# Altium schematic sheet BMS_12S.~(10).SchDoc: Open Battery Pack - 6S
size A3; Author: Morgane Vallée; Revision: 1.0; SheetNumber: 3; SheetTotal: 4
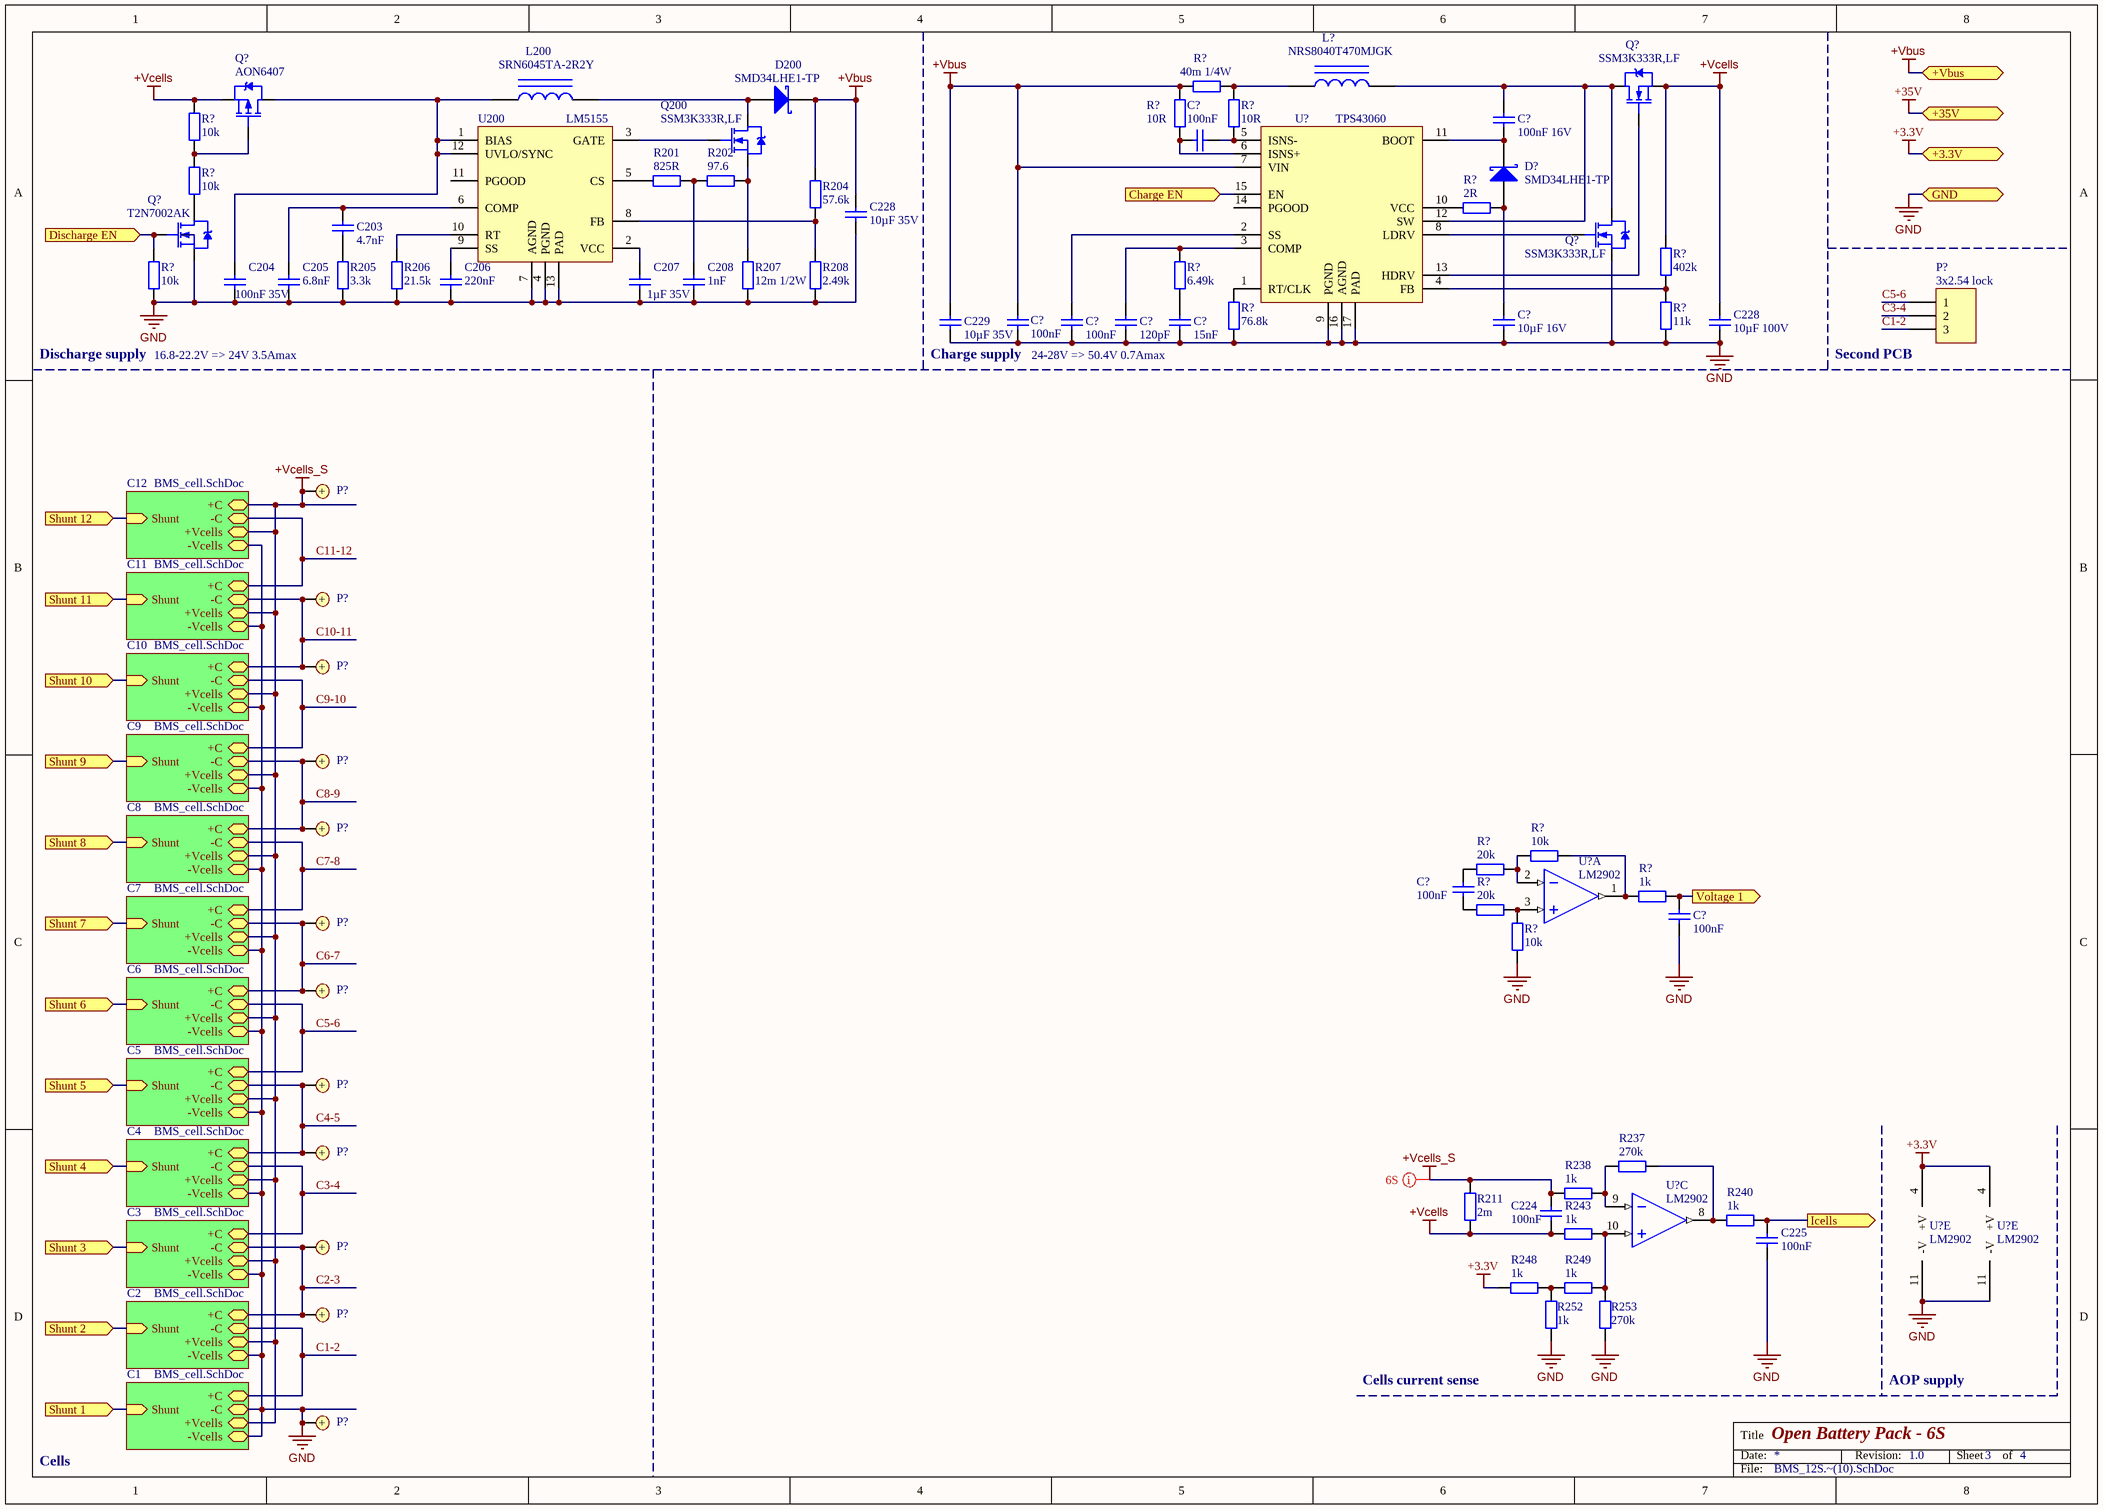
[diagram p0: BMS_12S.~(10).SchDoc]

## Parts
(Parts that share a designator on the sheet are numbered #1, #2 ... from top to bottom, then left to right.)
C203  4.7nF  [C0603]
C204  100nF 35V  [C0603]
C205  6.8nF  [C0603]
C206  220nF  [C0603]
C207  1µF 35V  [C0805]
C208  1nF  [C0603]
C224  100nF  [C0603]
C225  100nF  [C0603]
C228#1  10µF 35V  [C0603]
C228#2  10µF 100V  [C0603]
C229  10µF 35V  [C0603]
C?#1  100nF 16V  [C0603]
C?#2  100nF  [C0603]
C?#3  100nF  [C0603]
C?#4  120pF  [C0603]
C?#5  15nF  [C0603]
C?#6  10µF 16V  [C0805]
C?#7  100nF  [C0603]
C?#8  100nF  [C0603]
C?#9  100nF  [C0603]
D200  SMD34LHE1-TP  [SOD-123H]
D?  SMD34LHE1-TP  [SOD-123H]
L200  SRN6045TA-2R2Y  [SELF_SMD_8x8]
L?  NRS8040T470MJGK  [SELF_SMD_8x8]
P?#1  3x2.54 lock  [MOLEX KK 0022272031]
P?#2  Bat+  [Keystone 241]  (value not drawn)
P?#3  Bat+  [Keystone 241]  (value not drawn)
P?#4  Bat+  [Keystone 241]  (value not drawn)
P?#5  Bat+  [Keystone 241]  (value not drawn)
P?#6  Bat+  [Keystone 241]  (value not drawn)
P?#7  Bat+  [Keystone 241]  (value not drawn)
P?#8  Bat+  [Keystone 241]  (value not drawn)
P?#9  Bat+  [Keystone 241]  (value not drawn)
P?#10  Bat+  [Keystone 241]  (value not drawn)
P?#11  Bat+  [Keystone 241]  (value not drawn)
P?#12  Bat+  [Keystone 241]  (value not drawn)
P?#13  Bat+  [Keystone 241]  (value not drawn)
Q200  SSM3K333R,LF  [TI SOT-23-3 DBZ]
Q?#1  SSM3K333R,LF  [TI SOT-23-3 DBZ]
Q?#2  AON6407  [DIODES SOT-23-3]
Q?#3  T2N7002AK  [DIODES SOT-23-3]
Q?#4  SSM3K333R,LF  [TI SOT-23-3 DBZ]
R201  825R  [R0603]
R202  97.6  [R0603]
R204  57.6k  [R0603]
R205  3.3k  [R0603]
R206  21.5k  [R0603]
R207  12m 1/2W  [R1206]
R208  2.49k  [R0603]
R211  2m  [R1206]
R237  270k  [R0603]
R238  1k  [R0603]
R240  1k  [R0603]
R243  1k  [R0603]
R248  1k  [R0603]
R249  1k  [R0603]
R252  1k  [R0603]
R253  270k  [R0603]
R?#1  10R  [R0603]
R?#2  40m 1/4W  [R1206]
R?#3  10R  [R0603]
R?#4  10k  [R0603]
R?#5  10k  [R0603]
R?#6  2R  [R0603]
R?#7  402k  [R0603]
R?#8  10k  [R0603]
R?#9  6.49k  [R0603]
R?#10  76.8k  [R0603]
R?#11  11k  [R0603]
R?#12  10k  [R0603]
R?#13  20k  [R0603]
R?#14  1k  [R0603]
R?#15  20k  [R0603]
R?#16  10k  [R0603]
U200  LM5155  [TI WSON-12]
U?#1  TPS43060  [TI WQFN-16 RGH]
U?#2  LM2902  [Atmel SO-14 14S1]  (part A of 5)
U?#3  LM2902  [Atmel SO-14 14S1]  (part C of 5)
U?#4  LM2902  [Atmel SO-14 14S1]  (part E of 5)
U?#5  LM2902  [Atmel SO-14 14S1]  (part E of 5)

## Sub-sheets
C1 = BMS_cell.SchDoc: -C, +C, +Vcells, -Vcells, Shunt (in)
C2 = BMS_cell.SchDoc: -C, +C, +Vcells, -Vcells, Shunt (in)
C3 = BMS_cell.SchDoc: -C, +C, +Vcells, -Vcells, Shunt (in)
C4 = BMS_cell.SchDoc: -C, +C, +Vcells, -Vcells, Shunt (in)
C5 = BMS_cell.SchDoc: -C, +C, +Vcells, -Vcells, Shunt (in)
C6 = BMS_cell.SchDoc: -C, +C, +Vcells, -Vcells, Shunt (in)
C7 = BMS_cell.SchDoc: -C, +C, +Vcells, -Vcells, Shunt (in)
C8 = BMS_cell.SchDoc: -C, +C, +Vcells, -Vcells, Shunt (in)
C9 = BMS_cell.SchDoc: -C, +C, +Vcells, -Vcells, Shunt (in)
C10 = BMS_cell.SchDoc: -C, +C, +Vcells, -Vcells, Shunt (in)
C11 = BMS_cell.SchDoc: -C, +C, +Vcells, -Vcells, Shunt (in)
C12 = BMS_cell.SchDoc: -C, +C, +Vcells, -Vcells, Shunt (in)

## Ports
+3.3V, +35V, +Vbus, Charge EN (in), Discharge EN (in), GND, Icells (out), Shunt 1 (in), Shunt 2 (in), Shunt 3 (in), Shunt 4 (in), Shunt 5 (in), Shunt 6 (in), Shunt 7 (in), Shunt 8 (in), Shunt 9 (in), Shunt 10 (in), Shunt 11 (in), Shunt 12 (in), Voltage 1 (out)

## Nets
+3.3V: R248.2 U?#4.4(+V) U?#5.4(+V) ; port +3.3V
+Vbus: C228#1.1 C229.1 C?#7.2 D200.3(K) R204.2 R?#1.1 R?#2.2 U?#1.7(VIN) ; port +Vbus
+Vcells: C224.2 C228#2.1 Q?#1.2(S) Q?#2.2(S) R211.1 R243.2 R?#4.2 R?#7.2
+Vcells_S: C224.1 P?#2.1 R211.2 R238.1 ; sheet C1/+Vcells, sheet C2/+Vcells, sheet C3/+Vcells, sheet C4/+Vcells, sheet C5/+Vcells, sheet C6/+Vcells, sheet C7/+Vcells, sheet C8/+Vcells, sheet C9/+Vcells, sheet C10/+Vcells, sheet C11/+Vcells, sheet C12/+C, sheet C12/+Vcells
GND: C204.2 C205.2 C206.2 C207.2 C208.2 C225.2 C228#1.2 C228#2.2 C229.2 C?#3.2 C?#4.2 C?#5.2 C?#6.2 C?#7.1 C?#9.2 P?#13.1 Q?#3.2(S) Q?#4.2(S) R205.1 R206.1 R207.1 R208.1 R252.2 R253.1 R?#8.1 R?#10.1 R?#11.1 R?#16.2 U200.4(PGND) U200.7(AGND) U200.13(PAD) U?#1.9(PGND) U?#1.16(AGND) U?#1.17(PAD) U?#4.11(-V) U?#5.11(-V) ; port GND, sheet C1/-C, sheet C1/-Vcells, sheet C2/-Vcells, sheet C3/-Vcells, sheet C4/-Vcells, sheet C5/-Vcells, sheet C6/-Vcells, sheet C7/-Vcells, sheet C8/-Vcells, sheet C9/-Vcells, sheet C10/-Vcells, sheet C11/-Vcells, sheet C12/-Vcells
C1-2: P?#1.3 ; sheet C1/+C, sheet C2/-C
C2-3: P?#11.1 P?#12.1 ; sheet C2/+C, sheet C3/-C
C3-4: P?#1.2 ; sheet C3/+C, sheet C4/-C
C4-5: P?#9.1 P?#10.1 ; sheet C4/+C, sheet C5/-C
C5-6: P?#1.1 ; sheet C5/+C, sheet C6/-C
C6-7: P?#7.1 P?#8.1 ; sheet C6/+C, sheet C7/-C
C7-8: sheet C7/+C, sheet C8/-C
C8-9: P?#5.1 P?#6.1 ; sheet C8/+C, sheet C9/-C
C9-10: sheet C9/+C, sheet C10/-C
C10-11: P?#3.1 P?#4.1 ; sheet C10/+C, sheet C11/-C
C11-12: sheet C11/+C, sheet C12/-C
Charge EN: U?#1.15(EN) ; port Charge EN
Discharge EN: Q?#3.1(G) R?#8.2 ; port Discharge EN
Icells: C225.1 R240.1 ; port Icells
Shunt 1: port Shunt 1, sheet C1/Shunt
Shunt 2: port Shunt 2, sheet C2/Shunt
Shunt 3: port Shunt 3, sheet C3/Shunt
Shunt 4: port Shunt 4, sheet C4/Shunt
Shunt 5: port Shunt 5, sheet C5/Shunt
Shunt 6: port Shunt 6, sheet C6/Shunt
Shunt 7: port Shunt 7, sheet C7/Shunt
Shunt 8: port Shunt 8, sheet C8/Shunt
Shunt 9: port Shunt 9, sheet C9/Shunt
Shunt 10: port Shunt 10, sheet C10/Shunt
Shunt 11: port Shunt 11, sheet C11/Shunt
Shunt 12: port Shunt 12, sheet C12/Shunt
Voltage 1: C?#9.1 R?#14.1 ; port Voltage 1
NetC203_1: C203.1 C205.1 U200.6(COMP)
NetC203_2: C203.2 R205.2
NetC204_1: C204.1 L200.1 Q?#2.3(D) U200.1(BIAS) U200.12(UVLO/SYNC)
NetC206_1: C206.1 U200.9(SS)
NetC207_1: C207.1 U200.2(VCC)
NetC208_1: C208.1 R201.1 R202.2
NetC?#1_1: C?#1.1 L?.2 Q?#1.3(D) Q?#4.3(D) U?#1.12(SW)
NetC?#1_2: C?#1.2 D?.3(K) U?#1.11(BOOT)
NetC?#2_1: C?#2.1 R?#3.2 U?#1.5(ISNS-)
NetC?#2_2: C?#2.2 R?#1.2 U?#1.6(ISNS+)
NetC?#3_1: C?#3.1 U?#1.2(SS)
NetC?#4_1: C?#4.1 R?#9.2 U?#1.3(COMP)
NetC?#5_1: C?#5.1 R?#9.1
NetC?#6_1: C?#6.1 D?.1(A) R?#6.1
NetC?#8_1: C?#8.1 R?#13.1
NetC?#8_2: C?#8.2 R?#15.2
NetD200_1: D200.1(A) L200.2 Q200.3(D)
NetL?_1: L?.1 R?#2.1 R?#3.1
NetQ200_1: Q200.1(G) U200.3(GATE)
NetQ200_2: Q200.2(S) R202.1 R207.2
NetQ?#1_1: Q?#1.1(G) U?#1.13(HDRV)
NetQ?#2_1: Q?#2.1(G) R?#4.1 R?#5.2
NetQ?#3_3: Q?#3.3(D) R?#5.1
NetQ?#4_1: Q?#4.1(G) U?#1.8(LDRV)
NetR201_2: R201.2 U200.5(CS)
NetR204_1: R204.1 R208.2 U200.8(FB)
NetR206_2: R206.2 U200.10(RT)
NetR237_1: R237.1 R240.2 U?#3.8(OUT)
NetR237_2: R237.2 R238.2 U?#3.9(IN-)
NetR243_1: R243.1 R249.1 R253.2 U?#3.10(IN+)
NetR248_1: R248.1 R249.2 R252.1
NetR?#6_2: R?#6.2 U?#1.10(VCC)
NetR?#7_1: R?#7.1 R?#11.2 U?#1.4(FB)
NetR?#10_2: R?#10.2 U?#1.1(RT/CLK)
NetR?#12_1: R?#12.1 R?#13.2 U?#2.2(IN-)
NetR?#12_2: R?#12.2 R?#14.2 U?#2.1(OUT)
NetR?#15_1: R?#15.1 R?#16.1 U?#2.3(IN+)

Not connected (* = marked no-connect by the designer): U200 11(PGOOD); U?#1 14(PGOOD)

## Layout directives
net class 6S: +Vcells_S

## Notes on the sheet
- Discharge supply
- 16.8-22.2V => 24V 3.5Amax
- Charge supply
- (near C?#4) 24-28V => 50.4V 0.7Amax
- (near P?#1) Second PCB
- Cells current sense
- AOP supply
- Cells

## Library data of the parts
C203-C208 C224 C225 C228#1 C228#2 C229 C?#1-C?#9 = Cap: Capacitor
D200 D? = Diode BAT17
L200 L? = Inductor Iron: Magnetic-Core Inductor
P?#1 = Header 3: Header, 3-Pin
P?#2-P?#13 = Bat+: Battery contact +
Q200 Q?#1 Q?#3 Q?#4 = MOSFET_N
Q?#2 = MOSFET_P
R201 R202 R204-R208 R211 R237 R238 R240 R243 R248 R249 R252 R253 R?#1-R?#16 = Res2: Resistor
U200 = LM5155: 2.2-MHz Wide Input Nonsynchronous Boost, SEPIC, Flyback Controller
U?#1 = TPS43060: Low Quiescent Current Synchronous Boost  DC-DC Controller With Wide VIN Range
U?#2-U?#5 = LM2902: Low-power quad operational amplifiers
